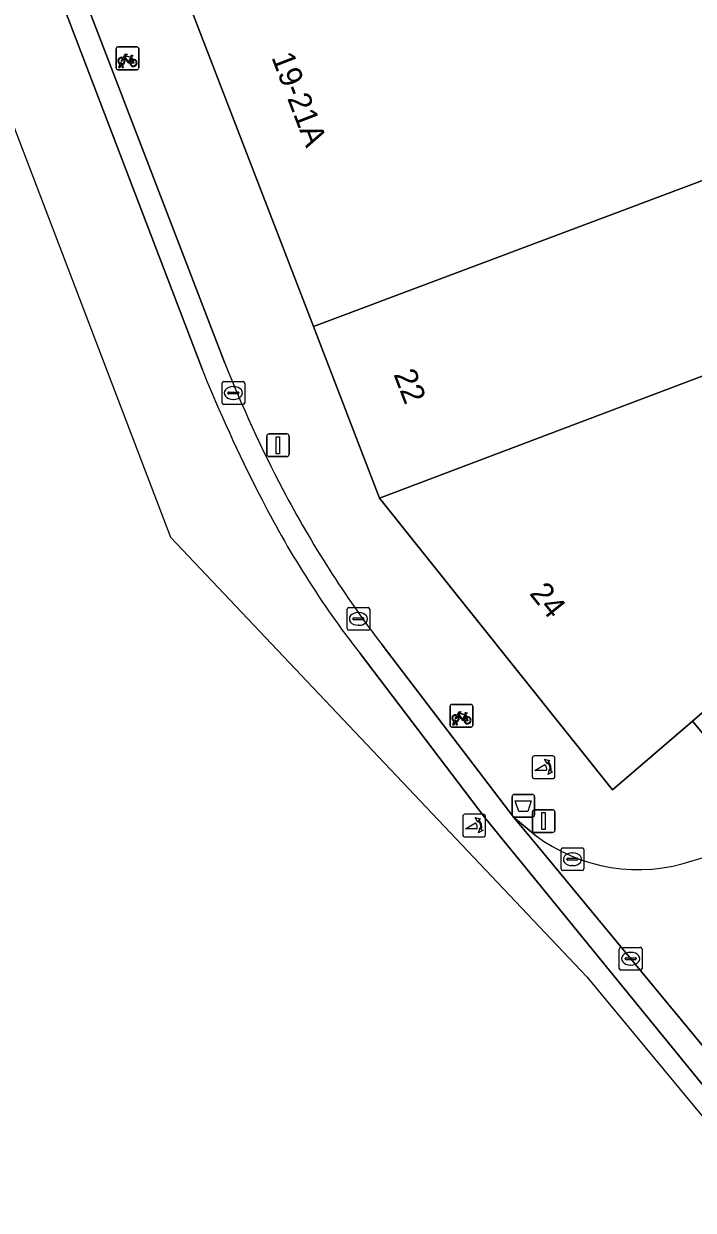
# Model space of a CAD drawing. Extents: x 160856 to 161310, y 384024 to 384878.
# Drawn here: x 160944.6 to 160974, y 384562.9 to 384615.1 of the extents above; entities that cross this region are included whole.
import ezdxf

# ---------------------------------------------------------------- set-up
doc = ezdxf.new("R2010")
doc.units = 0
for name, color, linetype in [('IMGEO_Afvalbak', 7, 'Continuous'), ('IMGEO_Fietsenrek', 7, 'Continuous'), ('IMGEO_Fietspad_gesloten', 7, 'Continuous'), ('IMGEO_Fietspad_open', 7, 'Continuous'), ('IMGEO_Kolk', 7, 'Continuous'), ('IMGEO_Lichtmast', 7, 'Continuous'), ('IMGEO_Pand', 7, 'Continuous'), ('IMGEO_Pand_nummerreeks', 7, 'Continuous'), ('IMGEO_Poller', 7, 'Continuous'), ('IMGEO_Rijbaan_lokaal_gesloten', 7, 'Continuous'), ('IMGEO_Rioolput', 7, 'Continuous'), ('IMGEO_Voetpad_open', 7, 'Continuous')]:
    doc.layers.add(name, color=color, linetype=linetype)

msp = doc.modelspace()

# ---------------------------------------------------------------- linework, layer by layer
at = {"layer": 'IMGEO_Afvalbak'}
for p, q in [((160966.058, 384580.295), (160966.058, 384581.095)), ((160966.058, 384581.095), (160966.058, 384580.295)), ((160966.158, 384581.195), (160966.948, 384581.195)), ((160966.948, 384581.195), (160966.158, 384581.195)), ((160967.048, 384581.095), (160967.048, 384580.295)), ((160967.048, 384580.295), (160967.048, 384581.095)), ((160966.948, 384580.195), (160966.158, 384580.195)), ((160966.158, 384580.195), (160966.948, 384580.195))]:
    msp.add_line(p, q, dxfattribs=at)
msp.add_lwpolyline([(160966.201, 384580.909), (160966.905, 384580.909), (160966.756, 384580.439), (160966.35, 384580.439), (160966.201, 384580.909)], dxfattribs=at)
for centre, start, end in [((160966.158, 384581.095), 90, 180), ((160966.158, 384581.095), 90, 180), ((160966.948, 384581.095), 0, 90), ((160966.948, 384581.095), 360, 90), ((160966.158, 384580.295), 180, 270), ((160966.158, 384580.295), 180, 270), ((160966.948, 384580.295), 270, 0), ((160966.948, 384580.295), 270, 0)]:
    msp.add_arc(centre, 0.1, start, end, dxfattribs=at)
at = {"layer": 'IMGEO_Fietsenrek'}
for p, q in [((160948.625, 384613.154), (160948.625, 384613.995)), ((160948.625, 384613.995), (160948.625, 384613.154)), ((160948.7, 384614.079), (160949.541, 384614.079)), ((160949.541, 384614.079), (160948.7, 384614.079)), ((160949.625, 384614.004), (160949.625, 384613.163)), ((160949.625, 384613.163), (160949.625, 384614.004)), ((160949.312, 384613.628), (160949.348, 384613.533)), ((160949.55, 384613.079), (160948.709, 384613.079)), ((160948.709, 384613.079), (160949.55, 384613.079)), ((160948.752, 384613.163), (160948.791, 384613.323)), ((160948.786, 384613.163), (160948.752, 384613.163)), ((160948.821, 384613.311), (160948.786, 384613.163)), ((160948.863, 384613.335), (160948.862, 384613.339)), ((160948.904, 384613.163), (160948.87, 384613.305)), ((160948.894, 384613.346), (160948.895, 384613.339)), ((160948.902, 384613.309), (160948.937, 384613.163)), ((160948.937, 384613.163), (160948.904, 384613.163)), ((160963.329, 384584.23), (160963.329, 384585.071)), ((160963.329, 384585.071), (160963.329, 384584.23)), ((160963.404, 384585.155), (160964.245, 384585.155)), ((160964.245, 384585.155), (160963.404, 384585.155)), ((160964.329, 384585.08), (160964.329, 384584.239)), ((160964.329, 384584.239), (160964.329, 384585.08)), ((160963.456, 384584.239), (160963.495, 384584.399)), ((160963.49, 384584.239), (160963.456, 384584.239)), ((160963.525, 384584.387), (160963.49, 384584.239)), ((160963.567, 384584.411), (160963.566, 384584.415)), ((160963.608, 384584.239), (160963.574, 384584.381)), ((160963.598, 384584.422), (160963.599, 384584.415)), ((160963.606, 384584.385), (160963.641, 384584.239)), ((160963.641, 384584.239), (160963.608, 384584.239)), ((160964.016, 384584.704), (160964.052, 384584.609)), ((160964.254, 384584.155), (160963.413, 384584.155)), ((160963.413, 384584.155), (160964.254, 384584.155))]:
    msp.add_line(p, q, dxfattribs=at)
for points in [[(160948.959, 384613.553), (160948.907, 384613.463), (160948.867, 384613.438), (160948.868, 384613.485), (160948.923, 384613.579)], [(160948.938, 384613.605), (160949.033, 384613.769), (160949.119, 384613.755), (160949.121, 384613.746), (160949.065, 384613.735), (160949.038, 384613.69), (160949.294, 384613.649)], [(160949.234, 384613.361), (160949.184, 384613.361), (160948.993, 384613.612), (160948.974, 384613.58)], [(160949.281, 384613.624), (160949.024, 384613.665), (160949.007, 384613.636), (160949.174, 384613.416), (160949.281, 384613.624)], [(160949.329, 384613.526), (160949.299, 384613.603), (160949.19, 384613.385), (160949.233, 384613.385)], [(160949.263, 384613.385), (160949.383, 384613.384), (160949.339, 384613.498)], [(160949.359, 384613.505), (160949.414, 384613.36), (160949.264, 384613.36)], [(160949.294, 384613.649), (160949.319, 384613.698), (160949.313, 384613.702), (160949.29, 384613.706), (160949.278, 384613.713), (160949.277, 384613.716), (160949.279, 384613.721), (160949.374, 384613.706), (160949.376, 384613.696), (160949.366, 384613.683), (160949.354, 384613.677), (160949.34, 384613.683), (160949.312, 384613.628)], [(160963.642, 384584.681), (160963.737, 384584.845), (160963.823, 384584.831), (160963.825, 384584.822), (160963.769, 384584.811), (160963.742, 384584.766), (160963.998, 384584.725)], [(160963.985, 384584.7), (160963.728, 384584.741), (160963.711, 384584.712), (160963.878, 384584.492), (160963.985, 384584.7)], [(160963.998, 384584.725), (160964.023, 384584.774), (160964.017, 384584.778), (160963.994, 384584.782), (160963.982, 384584.789), (160963.981, 384584.792), (160963.983, 384584.797), (160964.078, 384584.782), (160964.08, 384584.772), (160964.07, 384584.759), (160964.058, 384584.753), (160964.044, 384584.759), (160964.016, 384584.704)], [(160963.663, 384584.629), (160963.611, 384584.539), (160963.571, 384584.514), (160963.572, 384584.561), (160963.627, 384584.655)], [(160963.938, 384584.437), (160963.888, 384584.437), (160963.697, 384584.688), (160963.678, 384584.656)], [(160964.033, 384584.602), (160964.003, 384584.679), (160963.894, 384584.461), (160963.937, 384584.461)], [(160963.967, 384584.461), (160964.087, 384584.46), (160964.043, 384584.574)], [(160964.063, 384584.581), (160964.118, 384584.436), (160963.968, 384584.436)]]:
    msp.add_lwpolyline(points, dxfattribs=at)
for centre, radius, start, end in [((160948.703, 384614.001), 0.0779, 92.4484, 184.2845), ((160948.703, 384614.001), 0.0779, 92.4484, 184.2845), ((160949.547, 384614.001), 0.0779, 2.4484, 94.2845), ((160949.547, 384614.001), 0.0779, 2.4484, 94.2845), ((160948.865, 384613.464), 0.159, 62.6766, 242.1369), ((160948.865, 384613.464), 0.129, 63.3192, 238.903), ((160948.865, 384613.464), 0.129, 283.6043, 43.4302), ((160948.865, 384613.464), 0.159, 283.5766, 46.6042), ((160949.392, 384613.38), 0.159, 113.3408, 178.3217), ((160949.392, 384613.38), 0.159, 187.0065, 105.7708), ((160949.392, 384613.38), 0.129, 113.923, 177.9556), ((160949.392, 384613.38), 0.129, 188.6715, 104.5883), ((160948.703, 384613.157), 0.0779, 182.4484, 274.2845), ((160948.703, 384613.157), 0.0779, 182.4484, 274.2845), ((160948.845, 384613.335), 0.0499, 12.8025, 158.6934), ((160948.865, 384613.464), 0.159, 253.9967, 271.7867), ((160948.845, 384613.335), 0.0174, 12.8025, 163.4502), ((160948.865, 384613.464), 0.129, 253.415, 269.0204), ((160949.547, 384613.157), 0.0779, 272.4484, 4.2845), ((160949.547, 384613.157), 0.0779, 272.4484, 4.2845), ((160963.407, 384585.077), 0.0779, 92.4484, 184.2845), ((160963.407, 384585.077), 0.0779, 92.4484, 184.2845), ((160964.251, 384585.077), 0.0779, 2.4484, 94.2845), ((160964.251, 384585.077), 0.0779, 2.4484, 94.2845), ((160963.407, 384584.233), 0.0779, 182.4484, 274.2845), ((160963.407, 384584.233), 0.0779, 182.4484, 274.2845), ((160963.569, 384584.54), 0.159, 62.6766, 242.1369), ((160963.569, 384584.54), 0.129, 63.3192, 238.903), ((160963.549, 384584.411), 0.0499, 12.8025, 158.6934), ((160963.569, 384584.54), 0.159, 253.9967, 271.7867), ((160963.549, 384584.411), 0.0174, 12.8025, 163.4502), ((160963.569, 384584.54), 0.129, 253.415, 269.0204), ((160963.569, 384584.54), 0.129, 283.6043, 43.4302), ((160963.569, 384584.54), 0.159, 283.5766, 46.6042), ((160964.096, 384584.456), 0.159, 113.3408, 178.3217), ((160964.096, 384584.456), 0.159, 187.0065, 105.7708), ((160964.096, 384584.456), 0.129, 113.923, 177.9556), ((160964.096, 384584.456), 0.129, 188.6715, 104.5883), ((160964.251, 384584.233), 0.0779, 272.4484, 4.2845), ((160964.251, 384584.233), 0.0779, 272.4484, 4.2845)]:
    msp.add_arc(centre, radius, start, end, dxfattribs=at)
at = {"layer": 'IMGEO_Fietspad_gesloten'}
for points in [[(160952.428, 384599.868), (160937.604, 384638.593), (160892.484, 384755.839), (160890.883, 384755.238), (160892.527, 384749.494), (160889.824, 384754.841), (160889.132, 384754.582), (160951.015, 384592.51), (160969.346, 384573.161), (160977.866, 384562.895)], [(160977.866, 384562.895), (160978.487, 384563.462), (160966.529, 384578.127), (160965.859, 384578.948), (160964.841, 384580.196), (160959.37, 384587.387)]]:
    msp.add_lwpolyline(points, dxfattribs=at)
for centre, radius, start, end in [((161013.118, 384624.322), 65.432, 201.94626, 207.20544), ((160992.755, 384613.44), 42.348, 206.7074, 217.9685)]:
    msp.add_arc(centre, radius, start, end, dxfattribs=at)
at = {"layer": 'IMGEO_Fietspad_open'}
for points in [[(160921.747, 384682.423), (160893.385, 384756.183), (160892.484, 384755.839), (160937.604, 384638.593), (160952.428, 384599.868)], [(160953.42, 384600.161), (160938.279, 384639.478), (160931.483, 384657.104), (160921.747, 384682.423)], [(160959.37, 384587.387), (160964.841, 384580.196), (160965.859, 384578.948), (160966.529, 384578.127), (160978.487, 384563.462), (160979.348, 384564.156), (160978.54, 384565.18), (160967.308, 384578.769), (160966.142, 384580.179), (160960.339, 384587.77)]]:
    msp.add_lwpolyline(points, dxfattribs=at)
for centre, radius, start, end in [((161008.054, 384621.85), 58.782, 201.65248, 207.60958), ((161013.118, 384624.322), 65.432, 201.94626, 207.20544), ((160992.755, 384613.44), 42.348, 206.7074, 217.9685), ((160998.454, 384616.962), 48.009, 207.7503, 217.4487)]:
    msp.add_arc(centre, radius, start, end, dxfattribs=at)
at = {"layer": 'IMGEO_Kolk'}
for p, q in [((160953.365, 384599.353), (160954.217, 384599.353)), ((160953.29, 384598.427), (160953.29, 384599.279)), ((160953.549, 384598.847), (160953.549, 384598.859)), ((160953.592, 384598.896), (160953.99, 384598.896)), ((160953.778, 384599.133), (160953.803, 384599.133)), ((160954.033, 384598.859), (160954.033, 384598.847)), ((160954.291, 384599.279), (160954.291, 384598.427)), ((160954.217, 384598.353), (160953.365, 384598.353)), ((160953.987, 384598.81), (160953.589, 384598.81)), ((160953.801, 384598.573), (160953.776, 384598.573)), ((160958.796, 384588.489), (160958.796, 384589.341)), ((160958.871, 384589.415), (160959.723, 384589.415)), ((160959.055, 384588.909), (160959.055, 384588.921)), ((160959.098, 384588.958), (160959.496, 384588.958)), ((160959.284, 384589.195), (160959.309, 384589.195)), ((160959.539, 384588.921), (160959.539, 384588.909)), ((160959.797, 384589.341), (160959.797, 384588.489)), ((160959.723, 384588.415), (160958.871, 384588.415)), ((160959.493, 384588.872), (160959.095, 384588.872)), ((160959.307, 384588.635), (160959.282, 384588.635)), ((160968.217, 384577.914), (160968.217, 384578.766)), ((160968.292, 384578.84), (160969.144, 384578.84)), ((160968.705, 384578.62), (160968.73, 384578.62)), ((160969.218, 384578.766), (160969.218, 384577.914)), ((160968.476, 384578.334), (160968.476, 384578.346)), ((160968.914, 384578.297), (160968.516, 384578.297)), ((160968.519, 384578.383), (160968.917, 384578.383)), ((160968.728, 384578.06), (160968.703, 384578.06)), ((160968.96, 384578.346), (160968.96, 384578.334)), ((160969.144, 384577.84), (160968.292, 384577.84))]:
    msp.add_line(p, q, dxfattribs=at)
for points in [[(160953.365, 384599.353), (160954.217, 384599.353)], [(160953.29, 384598.427), (160953.29, 384599.279)], [(160954.291, 384599.279), (160954.291, 384598.427)], [(160954.217, 384598.353), (160953.365, 384598.353)], [(160958.796, 384588.489), (160958.796, 384589.341)], [(160958.871, 384589.415), (160959.723, 384589.415)], [(160959.797, 384589.341), (160959.797, 384588.489)], [(160959.723, 384588.415), (160958.871, 384588.415)], [(160968.217, 384577.914), (160968.217, 384578.766)], [(160968.292, 384578.84), (160969.144, 384578.84)], [(160969.218, 384578.766), (160969.218, 384577.914)], [(160969.144, 384577.84), (160968.292, 384577.84)]]:
    msp.add_lwpolyline(points, dxfattribs=at)
for centre, radius, start, end in [((160953.367, 384599.277), 0.0765, 91.552, 178.448), ((160953.367, 384599.277), 0.0765, 91.552, 178.448), ((160954.215, 384599.277), 0.0765, 1.552, 88.448), ((160954.215, 384599.277), 0.0765, 1.552, 88.448), ((160953.589, 384598.856), 0.0403, 85.8775, 175.7526), ((160953.586, 384598.846), 0.0366, 178.938, 274.7102), ((160953.99, 384598.853), 0.043, 264.8664, 352.4533), ((160953.994, 384598.858), 0.0386, 1.7309, 96.639), ((160953.367, 384598.429), 0.0765, 181.552, 268.448), ((160953.367, 384598.429), 0.0765, 181.552, 268.448), ((160954.215, 384598.429), 0.0765, 271.552, 358.448), ((160954.215, 384598.429), 0.0765, 271.552, 358.448), ((160958.873, 384589.339), 0.0765, 91.552, 178.448), ((160958.873, 384589.339), 0.0765, 91.552, 178.448), ((160959.095, 384588.918), 0.0403, 85.8775, 175.7526), ((160959.092, 384588.908), 0.0366, 178.938, 274.7102), ((160959.496, 384588.915), 0.043, 264.8664, 352.4533), ((160959.5, 384588.92), 0.0386, 1.7309, 96.639), ((160959.721, 384589.339), 0.0765, 1.552, 88.448), ((160959.721, 384589.339), 0.0765, 1.552, 88.448), ((160958.873, 384588.491), 0.0765, 181.552, 268.448), ((160958.873, 384588.491), 0.0765, 181.552, 268.448), ((160959.721, 384588.491), 0.0765, 271.552, 358.448), ((160959.721, 384588.491), 0.0765, 271.552, 358.448), ((160968.294, 384578.764), 0.0765, 91.552, 178.448), ((160968.294, 384578.764), 0.0765, 91.552, 178.448), ((160969.142, 384578.764), 0.0765, 1.552, 88.448), ((160969.142, 384578.764), 0.0765, 1.552, 88.448), ((160968.516, 384578.343), 0.0403, 85.8775, 175.7526), ((160968.513, 384578.333), 0.0366, 178.938, 274.7102), ((160968.917, 384578.34), 0.043, 264.8664, 352.4533), ((160968.921, 384578.345), 0.0386, 1.7309, 96.639), ((160968.294, 384577.916), 0.0765, 181.552, 268.448), ((160968.294, 384577.916), 0.0765, 181.552, 268.448), ((160969.142, 384577.916), 0.0765, 271.552, 358.448), ((160969.142, 384577.916), 0.0765, 271.552, 358.448)]:
    msp.add_arc(centre, radius, start, end, dxfattribs=at)
for centre, major_axis, ratio, start_param, end_param in [((160953.777, 384598.853), (-0.387, 0.002), 0.722429, 4.712389, 7.853982), ((160953.802, 384598.853), (-0.39, 0.002), 0.717154, 1.570796, 4.712389), ((160959.283, 384588.915), (-0.387, 0.002), 0.722429, 4.712389, 7.853982), ((160959.308, 384588.915), (-0.39, 0.002), 0.717154, 1.570796, 4.712389), ((160968.704, 384578.34), (-0.387, 0.002), 0.722429, 4.712389, 7.853982), ((160968.729, 384578.34), (-0.39, 0.002), 0.717154, 1.570796, 4.712389)]:
    msp.add_ellipse(centre, major_axis=major_axis, ratio=ratio, start_param=start_param, end_param=end_param, dxfattribs=at)
at = {"layer": 'IMGEO_Lichtmast'}
for p, q in [((160955.256, 384596.156), (160955.256, 384596.956)), ((160955.256, 384596.956), (160955.256, 384596.156)), ((160955.356, 384597.056), (160956.146, 384597.056)), ((160956.146, 384597.056), (160955.356, 384597.056)), ((160956.246, 384596.956), (160956.246, 384596.156)), ((160956.246, 384596.156), (160956.246, 384596.956)), ((160956.146, 384596.056), (160955.356, 384596.056)), ((160955.356, 384596.056), (160956.146, 384596.056)), ((160966.953, 384579.619), (160966.953, 384580.419)), ((160966.953, 384580.419), (160966.953, 384579.619)), ((160967.053, 384580.519), (160967.843, 384580.519)), ((160967.843, 384580.519), (160967.053, 384580.519)), ((160967.943, 384580.419), (160967.943, 384579.619)), ((160967.943, 384579.619), (160967.943, 384580.419)), ((160967.843, 384579.519), (160967.053, 384579.519)), ((160967.053, 384579.519), (160967.843, 384579.519))]:
    msp.add_line(p, q, dxfattribs=at)
for points in [[(160955.676, 384596.931), (160955.826, 384596.931), (160955.826, 384596.181), (160955.676, 384596.181), (160955.676, 384596.931)], [(160967.373, 384580.394), (160967.523, 384580.394), (160967.523, 384579.644), (160967.373, 384579.644), (160967.373, 384580.394)]]:
    msp.add_lwpolyline(points, dxfattribs=at)
for centre, start, end in [((160955.356, 384596.956), 90, 180), ((160955.356, 384596.956), 90, 180), ((160956.146, 384596.956), 0, 90), ((160956.146, 384596.956), 360, 90), ((160955.356, 384596.156), 180, 270), ((160955.356, 384596.156), 180, 270), ((160956.146, 384596.156), 270, 0), ((160956.146, 384596.156), 270, 0), ((160967.053, 384580.419), 90, 180), ((160967.053, 384580.419), 90, 180), ((160967.843, 384580.419), 0, 90), ((160967.843, 384580.419), 360, 90), ((160967.053, 384579.619), 180, 270), ((160967.053, 384579.619), 180, 270), ((160967.843, 384579.619), 270, 0), ((160967.843, 384579.619), 270, 0)]:
    msp.add_arc(centre, 0.1, start, end, dxfattribs=at)
at = {"layer": 'IMGEO_Pand'}
for points in [[(160957.323, 384601.772), (160985.981, 384612.527), (161000, 384617.833), (161002.264, 384618.717), (161000, 384624.44), (160998.052, 384629.357), (160983.529, 384628.84), (160983.224, 384628.829), (160951.057, 384618.029), (160951.527, 384616.811)], [(160957.323, 384601.772), (160960.23, 384594.229), (160986.187, 384604.043), (160990.689, 384598.828), (160994.768, 384602.349), (160985.981, 384612.527)], [(160990.689, 384598.828), (160986.187, 384604.043), (160960.23, 384594.229), (160970.483, 384581.386), (160973.995, 384584.418)]]:
    msp.add_lwpolyline(points, close=True, dxfattribs=at)
at = {"layer": 'IMGEO_Poller'}
for p, q in [((160966.946, 384582.787), (160966.946, 384581.98)), ((160966.946, 384582.787), (160966.946, 384581.98)), ((160967.848, 384582.882), (160967.04, 384582.882)), ((160967.848, 384582.882), (160967.04, 384582.882)), ((160967.942, 384581.98), (160967.942, 384582.787)), ((160967.942, 384581.98), (160967.942, 384582.787)), ((160967.04, 384581.885), (160967.848, 384581.885)), ((160967.04, 384581.885), (160967.848, 384581.885)), ((160963.891, 384580.221), (160963.891, 384579.414)), ((160963.891, 384580.221), (160963.891, 384579.414)), ((160964.793, 384580.316), (160963.985, 384580.316)), ((160964.793, 384580.316), (160963.985, 384580.316)), ((160964.887, 384579.414), (160964.887, 384580.221)), ((160964.887, 384579.414), (160964.887, 384580.221)), ((160963.985, 384579.319), (160964.793, 384579.319)), ((160963.985, 384579.319), (160964.793, 384579.319))]:
    msp.add_line(p, q, dxfattribs=at)
for points in [[(160967.625, 384582.611), (160967.613, 384582.538), (160967.488, 384582.743)], [(160967.488, 384582.743), (160967.719, 384582.677), (160967.648, 384582.645)], [(160967.581, 384582.238), (160967.068, 384582.238), (160967.498, 384582.513)], [(160967.641, 384582.066), (160967.707, 384582.297), (160967.737, 384582.229)], [(160967.773, 384582.202), (160967.845, 384582.191), (160967.641, 384582.066)], [(160964.57, 384580.045), (160964.558, 384579.972), (160964.433, 384580.177)], [(160964.433, 384580.177), (160964.664, 384580.111), (160964.593, 384580.079)], [(160964.526, 384579.672), (160964.013, 384579.672), (160964.443, 384579.947)], [(160964.586, 384579.5), (160964.652, 384579.731), (160964.682, 384579.663)], [(160964.718, 384579.636), (160964.79, 384579.625), (160964.586, 384579.5)]]:
    msp.add_lwpolyline(points, dxfattribs=at)
for centre, radius, start, end in [((160967.04, 384582.787), 0.0946, 90, 180), ((160967.04, 384582.787), 0.0946, 90, 180), ((160967.267, 384582.298), 0.516, 349.3569, 42.2912), ((160967.848, 384582.787), 0.0946, 0, 90), ((160967.848, 384582.787), 0.0946, 0, 90), ((160967.253, 384582.288), 0.332, 351.3247, 42.4854), ((160967.267, 384582.298), 0.476, 351.7527, 41.1691), ((160967.04, 384581.98), 0.0946, 180, 270), ((160967.04, 384581.98), 0.0946, 180, 270), ((160967.848, 384581.98), 0.0946, 270, 0), ((160967.848, 384581.98), 0.0946, 270, 0), ((160963.985, 384580.221), 0.0946, 90, 180), ((160963.985, 384580.221), 0.0946, 90, 180), ((160964.212, 384579.732), 0.476, 351.7527, 41.1691), ((160964.212, 384579.732), 0.516, 349.3569, 42.2912), ((160964.793, 384580.221), 0.0946, 0, 90), ((160964.793, 384580.221), 0.0946, 0, 90), ((160964.198, 384579.722), 0.332, 351.3247, 42.4854), ((160963.985, 384579.414), 0.0946, 180, 270), ((160963.985, 384579.414), 0.0946, 180, 270), ((160964.793, 384579.414), 0.0946, 270, 0), ((160964.793, 384579.414), 0.0946, 270, 0)]:
    msp.add_arc(centre, radius, start, end, dxfattribs=at)
at = {"layer": 'IMGEO_Rijbaan_lokaal_gesloten'}
msp.add_lwpolyline([(160967.063, 384579.409), (160966.142, 384580.179), (160967.308, 384578.769), (160978.54, 384565.18)], dxfattribs=at)
for centre, radius, start, end in [((160972.41, 384583.977), 5.922, 285.9389, 317.0588), ((160971.614, 384585.44), 7.556, 232.9605, 288.6936)]:
    msp.add_arc(centre, radius, start, end, dxfattribs=at)
at = {"layer": 'IMGEO_Rioolput'}
for p, q in [((160970.779, 384573.537), (160970.779, 384574.389)), ((160970.854, 384574.463), (160971.706, 384574.463)), ((160971.78, 384574.389), (160971.78, 384573.537)), ((160971.038, 384573.957), (160971.038, 384573.969)), ((160971.476, 384573.92), (160971.078, 384573.92)), ((160971.081, 384574.006), (160971.479, 384574.006)), ((160971.267, 384574.243), (160971.292, 384574.243)), ((160971.522, 384573.969), (160971.522, 384573.957)), ((160971.706, 384573.463), (160970.854, 384573.463)), ((160971.29, 384573.683), (160971.265, 384573.683))]:
    msp.add_line(p, q, dxfattribs=at)
for points in [[(160970.779, 384573.537), (160970.779, 384574.389)], [(160970.854, 384574.463), (160971.706, 384574.463)], [(160971.78, 384574.389), (160971.78, 384573.537)], [(160971.706, 384573.463), (160970.854, 384573.463)]]:
    msp.add_lwpolyline(points, dxfattribs=at)
for centre, radius, start, end in [((160970.856, 384574.387), 0.0765, 91.552, 178.448), ((160970.856, 384574.387), 0.0765, 91.552, 178.448), ((160971.704, 384574.387), 0.0765, 1.552, 88.448), ((160971.704, 384574.387), 0.0765, 1.552, 88.448), ((160971.078, 384573.966), 0.0403, 85.8775, 175.7526), ((160971.075, 384573.956), 0.0366, 178.938, 274.7102), ((160971.479, 384573.963), 0.043, 264.8664, 352.4533), ((160971.483, 384573.968), 0.0386, 1.7309, 96.639), ((160970.856, 384573.539), 0.0765, 181.552, 268.448), ((160970.856, 384573.539), 0.0765, 181.552, 268.448), ((160971.704, 384573.539), 0.0765, 271.552, 358.448), ((160971.704, 384573.539), 0.0765, 271.552, 358.448)]:
    msp.add_arc(centre, radius, start, end, dxfattribs=at)
for centre, major_axis, ratio, start_param, end_param in [((160971.266, 384573.963), (-0.387, 0.002), 0.722429, 4.712389, 7.853982), ((160971.291, 384573.963), (-0.39, 0.002), 0.717154, 1.570796, 4.712389)]:
    msp.add_ellipse(centre, major_axis=major_axis, ratio=ratio, start_param=start_param, end_param=end_param, dxfattribs=at)
at = {"layer": 'IMGEO_Voetpad_open'}
for points in [[(160929.276, 384674.544), (160928.927, 384675.368), (160928.003, 384677.547), (160926.724, 384680.788), (160925.586, 384683.954), (160921.747, 384682.423), (160931.483, 384657.104), (160933.049, 384657.72), (160939.775, 384640.046), (160938.279, 384639.478), (160953.42, 384600.161)], [(160977.218, 384580.587), (160973.995, 384584.418), (160970.483, 384581.386), (160960.23, 384594.229), (160957.323, 384601.772), (160951.527, 384616.811), (160951.057, 384618.029), (160949.182, 384622.895), (160948.94, 384623.522), (160944.938, 384633.907), (160944.571, 384634.966), (160940.157, 384646.186), (160937.67, 384652.508), (160937.451, 384653.082), (160937.202, 384653.736), (160935.494, 384658.22), (160935.209, 384658.967), (160933.47, 384663.572), (160929.276, 384674.544)], [(161043.184, 384645.796), (161041.458, 384644.107), (161037.434, 384640.168), (161033.664, 384636.809), (161027.384, 384631.214), (161017.955, 384622.48), (161000, 384606.866), (160994.768, 384602.349), (160990.689, 384598.828), (160973.995, 384584.418), (160977.218, 384580.587)], [(160960.339, 384587.77), (160966.142, 384580.179), (160967.063, 384579.409)]]:
    msp.add_lwpolyline(points, dxfattribs=at)
for centre, radius, start, end in [((161008.054, 384621.85), 58.782, 201.65248, 207.60958), ((160998.454, 384616.962), 48.009, 207.7503, 217.4487), ((160972.41, 384583.977), 5.922, 285.9389, 317.0588), ((160971.614, 384585.44), 7.556, 232.9605, 288.6936)]:
    msp.add_arc(centre, radius, start, end, dxfattribs=at)

# ---------------------------------------------------------------- texts
at = {"layer": 'IMGEO_Pand_nummerreeks'}
for s, rotation, p in [('19-21A', 291.0768, (160955.454, 384613.627)), ('22', 291.0768, (160960.829, 384599.682)), ('24', 308.676, (160966.792, 384590.021))]:
    msp.add_text(s, height=1, rotation=rotation, dxfattribs=at).set_placement(p)

doc.saveas('drawing.dxf')
